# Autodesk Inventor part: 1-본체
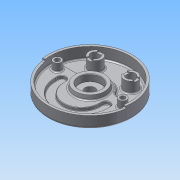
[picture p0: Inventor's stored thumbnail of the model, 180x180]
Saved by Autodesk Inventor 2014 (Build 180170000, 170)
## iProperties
Created: 2015-06
Part Number: 1-본체
Material: 알루미늄 6061
Document SubType Name: Modeling
Designer: Administrator
Density: 2.71 g/cm^3
Appearance: 알루미늄 - 평지
Mass: 1071.7 g
Surface Area: 1036.03 cm^2
Volume: 395.461 cm^3
Author: Administrator
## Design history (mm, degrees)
sketch "스케치1"
  geometry: C1 r 95 at (0, 0); 1 further point
  constraints: 1 centre point, 1 coincident
  dimensions: "d0" = 190 diameter of C1
extrude "돌출1" new body sketch "스케치1" distance "d1" = 32; taper "d2" = 0 deg
sketch "스케치2"
  geometry: L1 (45.033, 16)-(75.657, 16); L2 (-75.657, 16)-(-45.033, 16); C1 r 95 at (0, 0) reference; A1 r 42 centre (0, 0) between (-36.373, 21) and (36.373, 21); A2 r 90 centre (0, 0) between (-85.114, 29.25) and (85.114, 29.25); A3 r 10 centre (-75.657, 26) between (-85.114, 29.25) and (-75.657, 16); A4 r 10 centre (-45.033, 26) between (-45.033, 16) and (-36.373, 21); A5 r 10 centre (45.033, 26) between (36.373, 21) and (45.033, 16); A6 r 10 centre (75.657, 26) between (75.657, 16) and (85.114, 29.25)
  constraints: 12 point on circle, 12 tangent, 6 centre point, 4 end point, 3 equal radius, 2 coincident, 2 horizontal
  dimensions: "d3" = 84 diameter of A1; "d4" = 180 diameter of A2; "d6" = 20 diameter of A3; "d7" = 16 distance from line of C1.centre L2
extrude "돌출2" cut sketch "스케치2" distance "d8" = 25; taper "d9" = 0 deg
extrude "돌출3" cut sketch "스케치2" distance "d10" = 18; taper "d11" = 0 deg
sketch "스케치3"
  geometry: L1 (-75.657, 16)-(-45.033, 16) reference; L2 (-59, -19)-(-59, -14); L3 (-41, -19)-(-41, -14); L4 (41, -19)-(41, -14); L5 (59, -19)-(59, -14); A1 r 90 centre (0, 0) between (-85.114, 29.25) and (85.114, 29.25) reference; A2 r 59 centre (0, -19) between (-59, -19) and (59, -19); A3 r 41 centre (0, -19) between (-41, -19) and (41, -19); A4 r 9 centre (50, -14) between (59, -14) and (41, -14); A5 r 9 centre (-50, -14) between (-41, -14) and (-59, -14); 1 further point
  constraints: 8 end point, 8 point on circle, 6 tangent, 4 centre point, 3 parallel, 2 coincident, 1 perpendicular, 1 vertical alignment
  dimensions: "d12" = 19 distance of point (0, -19) A1.centre; "d13" = 118 diameter of A2; "d14" = 82 diameter of A3; "d15" = 5 vertical distance of A2.centre A5.centre; "d16" = 5 vertical distance of point (0, -19) A4.centre; "d17" = 18 diameter of A5; "d18" = 18 diameter of A4
extrude "돌출4" cut sketch "스케치3" distance "d19" = 7; taper "d20" = 0 deg
sketch "스케치4"
  geometry: C1 r 15 at (-40, 52); C2 r 15 at (40, 52); A1 r 42 centre (0, 0) between (36.373, 21) and (-36.373, 21) reference
  constraints: 2 centre point, 1 equal radius, 1 horizontal alignment
  dimensions: "d21" = 30 diameter of C1; "d22" = 40 horizontal distance of A1.centre C1.centre; "d23" = 80 distance of C2.centre C1.centre; "d24" = 52 vertical distance of A1.centre C2.centre
extrude "돌출5" join sketch "스케치4" stored distance "d25" = 7; taper "d26" = 0 deg
sketch "스케치6"
  geometry: C1 r 15 at (0, 0) reference; C2 r 15 at (80, 0) reference; 3 further points
  constraints: 2 coincident
hole "구멍1" sketch "스케치6" at (0, 0), (80, 0) diameter "d34" = 20; stored, may be unused: countersink angle "d38" = 90 deg, drill point angle "d40" = 118 deg; dims "d35" = 6, "d36" = 4, "d37" = 2, "d39" = 8
sketch "스케치5"
  geometry: L1 (-6, -15)-(6, -15); L2 (6, -15)-(6, 15); L3 (6, 15)-(-6, 15); L4 (-6, 15)-(-6, -15); L5 (-6, -15)-(6, 15); L6 (6, -15)-(-6, 15); L7 (65, 6)-(95, 6); L8 (95, 6)-(95, -6); L9 (95, -6)-(65, -6); L10 (65, -6)-(65, 6); L11 (65, 6)-(95, -6); L12 (95, 6)-(65, -6); C1 r 15 at (0, 0) reference; C2 r 15 at (80, 0) reference; 1 further point
  constraints: 24 end point, 4 midpoint, 4 parallel, 2 horizontal, 2 perpendicular
  dimensions: "d28" = 12 distance of L2.end L3.end; "d29" = 12 distance of L9.end L7.start; "d30" = 30 distance of L1.end L2.end; "d31" = 30 distance of L8.end L9.end
extrude "돌출6" cut sketch "스케치5" distance "d32" = 3; taper "d33" = 0 deg
sketch "스케치7"
  geometry: C1 r 35 at (0, 0); A1 r 42 centre (0, 0) between (36.373, 21) and (-36.373, 21) reference
  constraints: 1 centre point, 1 coincident
  dimensions: "d41" = 70 diameter of C1
extrude "돌출7" join sketch "스케치7" distance "d42" = 10; taper "d43" = -10 deg
sketch "스케치8"
  geometry: C1 r 35 at (0, 0) reference; C2 r 9 at (-74, 0); C3 r 9 at (74, 0)
  constraints: 2 centre point, 2 horizontal alignment, 1 equal radius
  dimensions: "d44" = 18 diameter of C2; "d45" = 148 distance of C3.centre C2.centre; "d46" = 74 distance of C1.centre C3.centre
extrude "돌출8" join sketch "스케치8" distance "d47" = 18; taper "d48" = 0 deg
sketch "스케치9"
  geometry: C1 r 95 at (0, 0) reference; C2 r 26 at (0, 0)
  constraints: 1 centre point, 1 coincident
  dimensions: "d49" = 52 diameter of C2
extrude "돌출9" join sketch "스케치9" distance "d50" = 12; taper "d51" = -15 deg
hole "구멍2" diameter "d54" = 23; stored, may be unused: countersink angle "d58" = 90 deg, drill point angle "d60" = 118 deg; dims "d52" = 10, "d53" = 10, "d55" = 6, "d56" = 50, "d57" = 15, "d59" = 8
sketch "스케치10"
  geometry: C1 r 9 at (-74, 0) reference; C2 r 9 at (74, 0) reference; 2 further points
  constraints: 2 coincident
hole "구멍3" sketch "스케치10" at (-74, 0), (74, 0) diameter "d61" = 11; stored, may be unused: countersink angle "d65" = 90 deg, drill point angle "d67" = 118 deg; dims "d62" = 6, "d63" = 18, "d64" = 11, "d66" = 8
sketch "스케치11"
  geometry: L1 (95, 0)-(90, 0); L2 (0, 0)-(89.124, -12.526); L3 (0, 0)-(-89.124, -12.526); L4 (90, 0)-(-90, 0); L5 (89.124, -12.526)-(94.075, -13.221); L6 (-89.124, -12.526)-(-94.075, -13.221); L7 (-90, 0)-(-95, 0); A1 r 95 centre (0, 0) between (-95, 0) and (-94.075, -13.221) reference; A2 r 90 centre (0, 0) between (90, 0) and (89.124, -12.526) reference
  constraints: 14 end point, 8 point on circle, 3 horizontal, 1 coincident, 1 midpoint, 1 point on line
  dimensions: "d68" = 8 deg angle of L1 L2; "d69" = 8 deg angle of L1 L3; "d70" = 8 deg angle of L7 L6; "d71" = 8 deg angle of L1 L5
extrude "돌출10" cut sketch "스케치11" distance "d72" = 5; taper "d73" = 0 deg
sketch "스케치12"
  geometry: C1 r 95 at (0, 0) reference; C2 r 68 at (0, 0)
  constraints: 1 centre point, 1 coincident, 1 other
  dimensions: "d74" = 136 diameter of C2
feature "엠보싱1" sketch "스케치12" dims "d75" = 0.5, "d76" = 0
fillet "모깎기1" dims "d77" = 0.3, "d78" = 1
fillet "모깎기2" dims "d79" = 3, "d83" = 5
chamfer "모따기1" distance "d80" = 1; stored, may be unused: second distance "d81" = 2, angle "d82" = 45 deg
node "솔리드1"
other parameters: "d5" = 16
